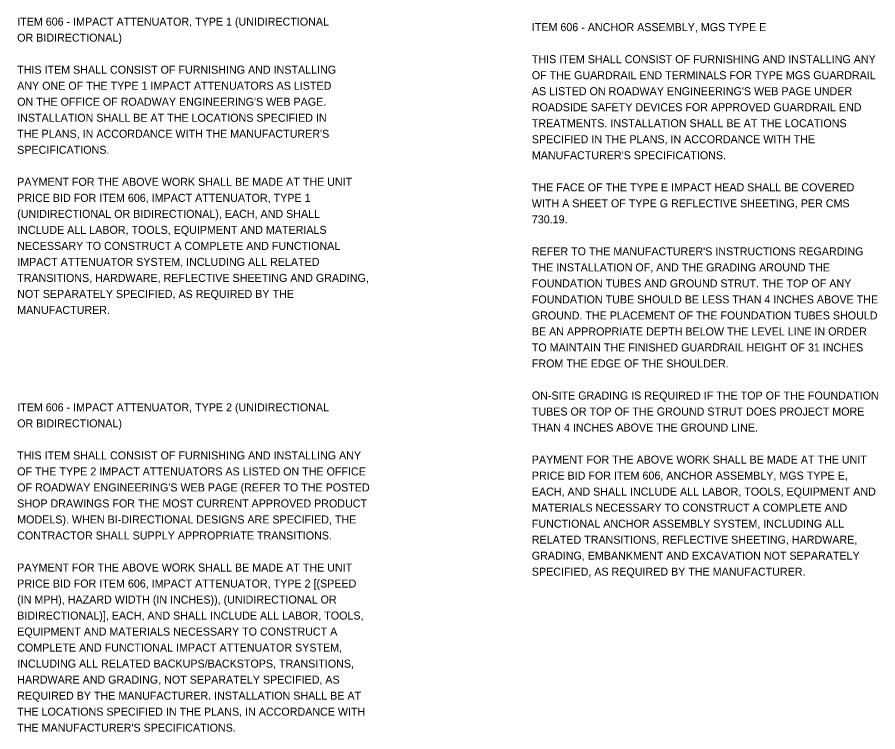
# Model space of a CAD drawing. Extents: x 11857.5 to 11911.9, y 383.2 to 429.7.
# Drawn here: x 11896.81 to 11911.85, y 394.28 to 406.77 of the extents above; entities that cross this region are included whole.
import ezdxf

# ---------------------------------------------------------------- set-up
doc = ezdxf.new("R2010")
doc.units = 0
doc.layers.add('SH_Text', color=7, linetype='Continuous')

msp = doc.modelspace()

# ---------------------------------------------------------------- texts
at = {"layer": 'SH_Text'}
for s, p in [('ITEM 606 - IMPACT ATTENUATOR, TYPE 1 (UNIDIRECTIONAL', (11896.809, 406.625)), ('ITEM 606 - ANCHOR ASSEMBLY, MGS TYPE E', (11905.806, 406.529)), ('OR BIDIRECTIONAL)', (11896.809, 406.345)), ('THIS ITEM SHALL CONSIST OF FURNISHING AND INSTALLING ANY', (11905.806, 405.969)), ('THIS ITEM SHALL CONSIST OF FURNISHING AND INSTALLING', (11896.809, 405.785)), ('OF THE GUARDRAIL END TERMINALS FOR TYPE MGS GUARDRAIL', (11905.806, 405.689)), ('ANY ONE OF THE TYPE 1 IMPACT ATTENUATORS AS LISTED', (11896.809, 405.505)), ("AS LISTED ON ROADWAY ENGINEERING'S WEB PAGE UNDER", (11905.806, 405.409)), ("ON THE OFFICE OF ROADWAY ENGINEERING'S WEB PAGE.", (11896.809, 405.225)), ('ROADSIDE SAFETY DEVICES FOR APPROVED GUARDRAIL END', (11905.806, 405.129)), ('INSTALLATION SHALL BE AT THE LOCATIONS SPECIFIED IN', (11896.809, 404.945)), ('TREATMENTS. INSTALLATION SHALL BE AT THE LOCATIONS', (11905.806, 404.849)), ("THE PLANS, IN ACCORDANCE WITH THE MANUFACTURER'S", (11896.809, 404.665)), ('SPECIFIED IN THE PLANS, IN ACCORDANCE WITH THE', (11905.806, 404.569)), ('SPECIFICATIONS.', (11896.809, 404.385)), ("MANUFACTURER'S SPECIFICATIONS.", (11905.806, 404.289)), ('PAYMENT FOR THE ABOVE WORK SHALL BE MADE AT THE UNIT', (11896.809, 403.825)), ('THE FACE OF THE TYPE E IMPACT HEAD SHALL BE COVERED', (11905.806, 403.729)), ('PRICE BID FOR ITEM 606, IMPACT ATTENUATOR, TYPE 1', (11896.809, 403.545)), ('WITH A SHEET OF TYPE G REFLECTIVE SHEETING, PER CMS', (11905.806, 403.449)), ('(UNIDIRECTIONAL OR BIDIRECTIONAL), EACH, AND SHALL', (11896.809, 403.265)), ('730.19.', (11905.806, 403.169)), ('INCLUDE ALL LABOR, TOOLS, EQUIPMENT AND MATERIALS', (11896.809, 402.985)), ('NECESSARY TO CONSTRUCT A COMPLETE AND FUNCTIONAL', (11896.809, 402.705)), ("REFER TO THE MANUFACTURER'S INSTRUCTIONS REGARDING", (11905.806, 402.609)), ('IMPACT ATTENUATOR SYSTEM, INCLUDING ALL RELATED', (11896.809, 402.425)), ('THE INSTALLATION OF, AND THE GRADING AROUND THE', (11905.806, 402.329)), ('TRANSITIONS, HARDWARE, REFLECTIVE SHEETING AND GRADING,', (11896.809, 402.145)), ('FOUNDATION TUBES AND GROUND STRUT. THE TOP OF ANY', (11905.806, 402.049)), ('NOT SEPARATELY SPECIFIED, AS REQUIRED BY THE', (11896.809, 401.865)), ('FOUNDATION TUBE SHOULD BE LESS THAN 4 INCHES ABOVE THE', (11905.806, 401.769)), ('MANUFACTURER.', (11896.809, 401.585)), ('GROUND. THE PLACEMENT OF THE FOUNDATION TUBES SHOULD', (11905.806, 401.489)), ('BE AN APPROPRIATE DEPTH BELOW THE LEVEL LINE IN ORDER', (11905.806, 401.209)), ('TO MAINTAIN THE FINISHED GUARDRAIL HEIGHT OF 31 INCHES', (11905.806, 400.929)), ('FROM THE EDGE OF THE SHOULDER.', (11905.806, 400.649)), ('ON-SITE GRADING IS REQUIRED IF THE TOP OF THE FOUNDATION', (11905.806, 400.089)), ('ITEM 606 - IMPACT ATTENUATOR, TYPE 2 (UNIDIRECTIONAL', (11896.809, 399.882)), ('TUBES OR TOP OF THE GROUND STRUT DOES PROJECT MORE', (11905.806, 399.809)), ('OR BIDIRECTIONAL)', (11896.809, 399.602)), ('THAN 4 INCHES ABOVE THE GROUND LINE.', (11905.806, 399.529)), ('THIS ITEM SHALL CONSIST OF FURNISHING AND INSTALLING ANY', (11896.809, 399.042)), ('PAYMENT FOR THE ABOVE WORK SHALL BE MADE AT THE UNIT', (11905.806, 398.969)), ('OF THE TYPE 2 IMPACT ATTENUATORS AS LISTED ON THE OFFICE', (11896.809, 398.762)), ('PRICE BID FOR ITEM 606, ANCHOR ASSEMBLY, MGS TYPE E,', (11905.806, 398.689)), ("OF ROADWAY ENGINEERING'S WEB PAGE (REFER TO THE POSTED", (11896.809, 398.482)), ('EACH, AND SHALL INCLUDE ALL LABOR, TOOLS, EQUIPMENT AND', (11905.806, 398.409)), ('SHOP DRAWINGS FOR THE MOST CURRENT APPROVED PRODUCT', (11896.809, 398.202)), ('MATERIALS NECESSARY TO CONSTRUCT A COMPLETE AND', (11905.806, 398.129)), ('MODELS). WHEN BI-DIRECTIONAL DESIGNS ARE SPECIFIED, THE', (11896.809, 397.922)), ('FUNCTIONAL ANCHOR ASSEMBLY SYSTEM, INCLUDING ALL', (11905.806, 397.849)), ('CONTRACTOR SHALL SUPPLY APPROPRIATE TRANSITIONS.', (11896.809, 397.642)), ('RELATED TRANSITIONS, REFLECTIVE SHEETING, HARDWARE,', (11905.806, 397.569)), ('GRADING, EMBANKMENT AND EXCAVATION NOT SEPARATELY', (11905.806, 397.289)), ('PAYMENT FOR THE ABOVE WORK SHALL BE MADE AT THE UNIT', (11896.809, 397.082)), ('SPECIFIED, AS REQUIRED BY THE MANUFACTURER.', (11905.806, 397.009)), ('PRICE BID FOR ITEM 606, IMPACT ATTENUATOR, TYPE 2 [(SPEED', (11896.809, 396.802)), ('(IN MPH), HAZARD WIDTH (IN INCHES)), (UNIDIRECTIONAL OR', (11896.809, 396.522)), ('BIDIRECTIONAL)], EACH, AND SHALL INCLUDE ALL LABOR, TOOLS,', (11896.809, 396.242)), ('EQUIPMENT AND MATERIALS NECESSARY TO CONSTRUCT A', (11896.809, 395.962)), ('COMPLETE AND FUNCTIONAL IMPACT ATTENUATOR SYSTEM,', (11896.809, 395.682)), ('INCLUDING ALL RELATED BACKUPS/BACKSTOPS, TRANSITIONS,', (11896.809, 395.402)), ('HARDWARE AND GRADING, NOT SEPARATELY SPECIFIED, AS', (11896.809, 395.122)), ('REQUIRED BY THE MANUFACTURER. INSTALLATION SHALL BE AT', (11896.809, 394.842)), ('THE LOCATIONS SPECIFIED IN THE PLANS, IN ACCORDANCE WITH', (11896.809, 394.562)), ("THE MANUFACTURER'S SPECIFICATIONS.", (11896.809, 394.282))]:
    msp.add_text(s, height=0.14, dxfattribs=at).set_placement(p)

doc.saveas('drawing.dxf')
